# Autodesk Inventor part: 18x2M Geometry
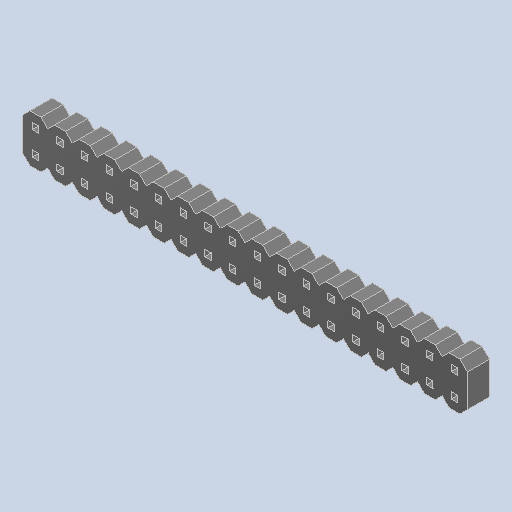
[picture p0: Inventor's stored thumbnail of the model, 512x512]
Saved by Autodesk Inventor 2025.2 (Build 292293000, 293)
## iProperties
Created: 2025-04
Part Number: 18x2M Geometry
Material: Generic
Description: PART-18x2M Geometry-DESC
Document SubType Name: Modeling
Designer: BennF
Density: 1 g/cm^3
Appearance: Default
Author: BennF
Revision Number: NONE
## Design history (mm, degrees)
feature "18"
body "Solid1"
